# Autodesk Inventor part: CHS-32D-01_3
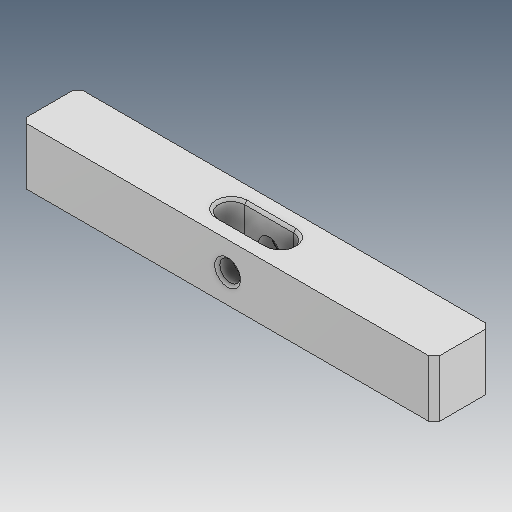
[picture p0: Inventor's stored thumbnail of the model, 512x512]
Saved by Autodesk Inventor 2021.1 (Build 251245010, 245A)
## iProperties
Created: 2021-05
Part Number: CHS-32D-01_3
Material: Ogólny
Document SubType Name: Modeling
Designer: user
Density: 1 g/cm^3
Appearance: Domyślna
Author: user
Revision Number: ÈÎºÎ
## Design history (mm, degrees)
feature "ÊäÈë1"
node "Bryła1"
